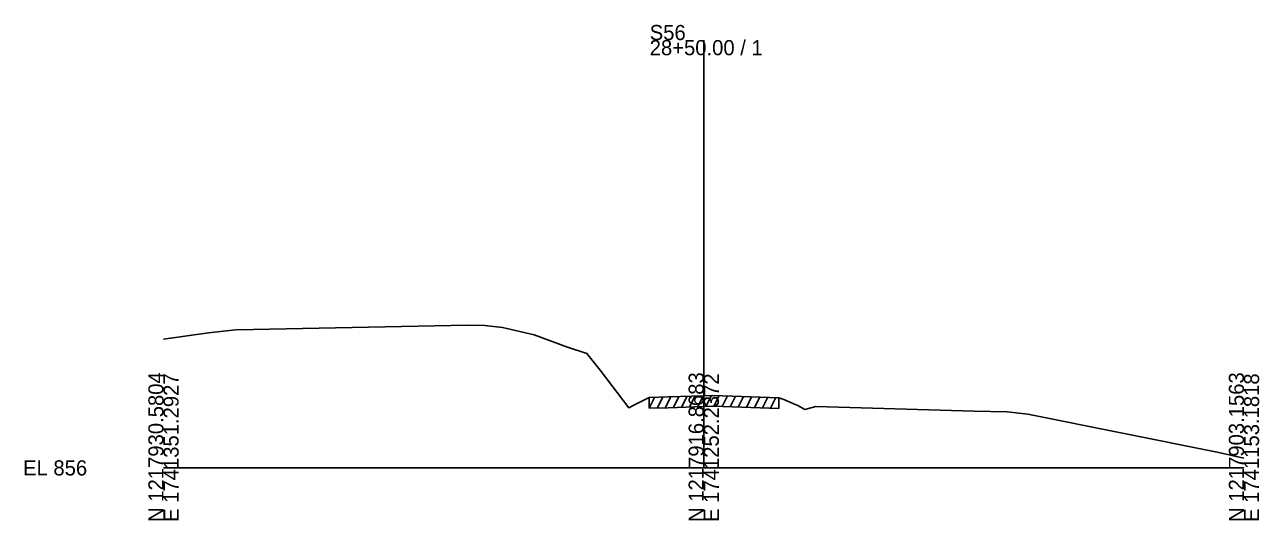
# Model space of a CAD drawing. Extents: x -26 to 1203, y -10 to 19541.
# Drawn here: x -25.7 to 202.8, y 3490.3 to 3582 of the extents above; entities that cross this region are included whole.
import ezdxf

# ---------------------------------------------------------------- set-up
doc = ezdxf.new("R2010")
doc.units = 0
for name, color, linetype in [('RD_GPK_XS_Cell', 7, 'Continuous'), ('RD_XS_ExGround', 7, 'Continuous'), ('RD_XS_ExPaveRet', 7, 'Continuous'), ('RD_XS_TX_Elev_EX', 7, 'Continuous')]:
    doc.layers.add(name, color=color, linetype=linetype)

msp = doc.modelspace()

# ---------------------------------------------------------------- linework, layer by layer
at = {"layer": 'RD_GPK_XS_Cell'}
for p, q in [((100, 3500), (100, 3579.14)), ((0, 3500), (100, 3500)), ((100, 3500), (200, 3500))]:
    msp.add_line(p, q, dxfattribs=at)
at = {"layer": 'RD_XS_ExGround'}
msp.add_lwpolyline([(0, 3523.79), (8.31, 3524.99), (13.31, 3525.53), (16.59, 3525.59), (56.3, 3526.38), (59.51, 3526.32), (62.76, 3526), (68.59, 3524.6), (74.78, 3522.34), (78.37, 3521.16), (80.84, 3518.07), (86.14, 3511.1), (87.04, 3511.63), (89.89, 3513.02), (93.39, 3513.13), (100, 3513.36), (101.66, 3513.42), (105.29, 3513.3), (113.92, 3512.99), (114.84, 3512.64), (116.8, 3511.81), (117.4, 3511.52), (118.72, 3510.8), (119.42, 3510.97), (120.75, 3511.34), (150.08, 3510.51), (156.15, 3510.35), (159.97, 3509.96), (195.05, 3502.91), (200, 3501.83)], dxfattribs=at)
at = {"layer": 'RD_XS_ExPaveRet'}
for p, q in [((89.89, 3511.02), (90.9, 3513.05)), ((89.89, 3511.02), (89.89, 3513.02)), ((91.39, 3511.07), (92.4, 3513.1)), ((92.89, 3511.11), (93.9, 3513.14)), ((94.39, 3511.16), (95.41, 3513.2)), ((95.89, 3511.22), (96.91, 3513.25)), ((97.39, 3511.27), (98.41, 3513.31)), ((98.89, 3511.32), (99.91, 3513.36)), ((100.39, 3511.38), (101.41, 3513.41)), ((101.89, 3511.41), (102.87, 3513.38)), ((103.39, 3511.36), (104.37, 3513.33)), ((104.89, 3511.31), (105.87, 3513.28)), ((106.39, 3511.26), (107.37, 3513.22)), ((107.89, 3511.2), (108.87, 3513.17)), ((109.39, 3511.15), (110.37, 3513.11)), ((110.89, 3511.1), (111.87, 3513.06)), ((112.39, 3511.04), (113.37, 3513.01)), ((113.92, 3512.99), (113.92, 3510.99)), ((89.89, 3511.02), (93.39, 3511.13)), ((93.39, 3511.13), (100, 3511.36)), ((100, 3511.36), (101.66, 3511.42)), ((101.66, 3511.42), (105.29, 3511.3)), ((105.29, 3511.3), (113.92, 3510.99))]:
    msp.add_line(p, q, dxfattribs=at)

# ---------------------------------------------------------------- texts
at = {"layer": 'RD_GPK_XS_Cell'}
for s, p in [('S56', (90, 3579.14)), ('28+50.00 / 1', (90, 3576.34)), ('EL 856', (-26, 3498.6))]:
    msp.add_text(s, height=2.8, dxfattribs=at).set_placement(p)
for s, p in [('N 1217930.5804', (0, 3490)), ('E 1741351.2927', (2.8, 3490)), ('N 1217916.8683', (100, 3490)), ('E 1741252.2372', (102.8, 3490)), ('N 1217903.1563', (200, 3490)), ('E 1741153.1818', (202.8, 3490))]:
    msp.add_text(s, height=2.8, rotation=90, dxfattribs=at).set_placement(p)
at = {"layer": 'RD_XS_TX_Elev_EX'}
msp.add_text('862.68', height=0.1, rotation=90, dxfattribs=at).set_placement((100.1, 3513.36))

doc.saveas('drawing.dxf')
